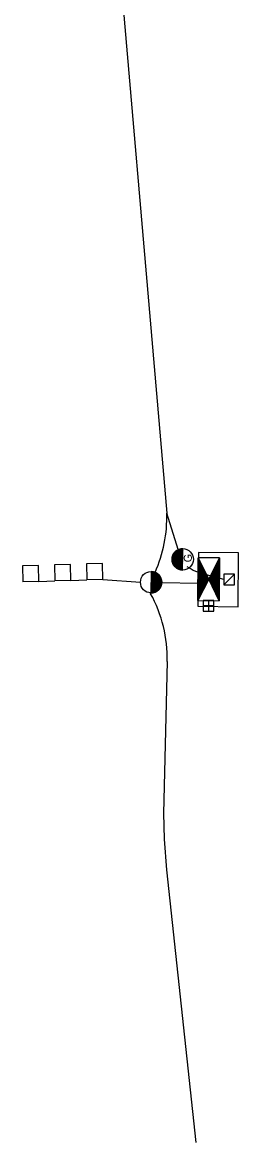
# Model space of a CAD drawing. Extents: x 584850 to 602551, y 145475 to 158627.
# Drawn here: x 585893.2 to 585974.3, y 152717.9 to 153137.7 of the extents above; entities that cross this region are included whole.
import ezdxf

# ---------------------------------------------------------------- set-up
doc = ezdxf.new("R2010")
doc.units = 0
doc.layers.add('Default', color=7, linetype='Continuous')

msp = doc.modelspace()

# ---------------------------------------------------------------- linework, layer by layer
at = {"layer": 'Default'}
for p, q in [((585951.7, 152940.13), (585947.39, 152953.8)), ((585953.38, 152940.5), (585949.39, 152936.66)), ((585953.45, 152940.24), (585949.4, 152936.33)), ((585953.45, 152939.9), (585949.42, 152936.02)), ((585953.01, 152940.47), (585949.43, 152937.03)), ((585953.44, 152939.56), (585949.47, 152935.74)), ((585952.6, 152940.41), (585949.49, 152937.42)), ((585952.14, 152940.3), (585949.65, 152937.9)), ((585951.52, 152940.04), (585949.94, 152938.52)), ((585950.79, 152939.54), (585953.39, 152936.84)), ((585950.98, 152939.69), (585953.4, 152937.18)), ((585951.18, 152939.83), (585953.4, 152937.52)), ((585951.39, 152939.96), (585953.41, 152937.86)), ((585951.61, 152940.08), (585953.41, 152938.2)), ((585951.84, 152940.18), (585953.42, 152938.54)), ((585952.08, 152940.28), (585953.43, 152938.88)), ((585952.34, 152940.35), (585953.43, 152939.22)), ((585952.61, 152940.42), (585953.44, 152939.56)), ((585952.9, 152940.47), (585953.45, 152939.9)), ((585953.21, 152940.49), (585953.45, 152940.24)), ((585953.31, 152932.5), (585953.46, 152940.5)), ((585953.41, 152940.5), (585953.46, 152940.46)), ((585949.4, 152936.83), (585953.31, 152932.77)), ((585949.4, 152936.49), (585953.23, 152932.51)), ((585949.4, 152936.14), (585952.86, 152932.54)), ((585949.45, 152937.13), (585953.32, 152933.11)), ((585949.48, 152935.72), (585952.46, 152932.62)), ((585949.49, 152937.43), (585953.33, 152933.45)), ((585953.43, 152939.22), (585949.53, 152935.45)), ((585949.58, 152937.69), (585953.33, 152933.79)), ((585953.43, 152938.88), (585949.61, 152935.2)), ((585949.66, 152937.94), (585953.34, 152934.13)), ((585953.42, 152938.54), (585949.71, 152934.96)), ((585949.76, 152938.18), (585953.34, 152934.47)), ((585953.41, 152938.2), (585949.81, 152934.72)), ((585949.88, 152938.41), (585953.35, 152934.81)), ((585953.41, 152937.86), (585949.93, 152934.51)), ((585950, 152938.63), (585953.36, 152935.15)), ((585953.4, 152937.52), (585950.06, 152934.3)), ((585950.14, 152938.83), (585953.36, 152935.49)), ((585953.4, 152937.18), (585950.2, 152934.1)), ((585950.29, 152939.02), (585953.37, 152935.82)), ((585953.39, 152936.84), (585950.35, 152933.92)), ((585950.44, 152939.21), (585953.38, 152936.16)), ((585953.38, 152936.5), (585950.51, 152933.73)), ((585950.62, 152939.37), (585953.38, 152936.5)), ((585953.38, 152936.16), (585950.68, 152933.57)), ((585953.37, 152935.82), (585950.87, 152933.41)), ((585953.36, 152935.49), (585951.05, 152933.26)), ((585957.29, 152937.49), (585957.19, 152937.44)), ((585959.92, 152935.65), (585959.19, 152934.94)), ((585960.03, 152935.42), (585959.19, 152934.6)), ((585959.59, 152936.33), (585959.2, 152935.96)), ((585959.7, 152936.1), (585959.2, 152935.62)), ((585959.81, 152935.88), (585959.2, 152935.28)), ((585960.47, 152934.51), (585959.2, 152935.81)), ((585960.8, 152933.83), (585959.2, 152935.47)), ((585959.48, 152936.56), (585959.21, 152936.83)), ((585959.37, 152936.79), (585959.21, 152936.64)), ((585959.48, 152936.56), (585959.21, 152936.3)), ((585959.81, 152935.88), (585959.21, 152936.49)), ((585960.14, 152935.2), (585959.21, 152936.15)), ((585959.26, 152937.01), (585959.22, 152936.98)), ((585967.2, 152935.38), (585965.56, 152933.78)), ((585967.2, 152935.72), (585965.9, 152934.45)), ((585967.21, 152936.06), (585966.25, 152935.13)), ((585967.19, 152934.51), (585966.37, 152935.35)), ((585967.19, 152934.85), (585966.48, 152935.58)), ((585967.21, 152936.4), (585966.6, 152935.8)), ((585967.2, 152935.19), (585966.6, 152935.8)), ((585967.2, 152935.53), (585966.71, 152936.03)), ((585967.21, 152935.87), (585966.83, 152936.25)), ((585967.21, 152936.2), (585966.94, 152936.48)), ((585967.22, 152936.74), (585966.95, 152936.48)), ((585967.21, 152936.54), (585967.06, 152936.7)), ((585967.22, 152936.88), (585967.18, 152936.93)), ((585899.24, 152934.19), (585893.24, 152934.01)), ((585893.24, 152934.01), (585893.43, 152928.01)), ((585899.43, 152928.2), (585899.24, 152934.19)), ((585911.23, 152934.57), (585905.24, 152934.38)), ((585905.24, 152934.38), (585905.43, 152928.39)), ((585911.42, 152928.58), (585911.23, 152934.57)), ((585923.23, 152934.95), (585917.23, 152934.76)), ((585917.23, 152934.76), (585917.42, 152928.77)), ((585923.42, 152928.96), (585923.23, 152934.95)), ((585941.59, 152931.94), (585941.44, 152923.95)), ((585941.54, 152929.3), (585943.64, 152931.32)), ((585941.54, 152928.96), (585943.85, 152931.19)), ((585941.55, 152929.98), (585943.2, 152931.57)), ((585941.55, 152929.64), (585943.42, 152931.45)), ((585941.56, 152930.32), (585942.95, 152931.66)), ((585941.57, 152931), (585942.43, 152931.83)), ((585941.57, 152930.66), (585942.71, 152931.76)), ((585941.58, 152931.34), (585942.15, 152931.88)), ((585945.45, 152927.32), (585941.58, 152931.34)), ((585941.59, 152931.94), (585941.59, 152931.94)), ((585941.59, 152931.94), (585941.59, 152931.94)), ((585941.59, 152931.68), (585941.85, 152931.93)), ((585945.5, 152927.62), (585941.59, 152931.68)), ((585945.5, 152927.96), (585941.67, 152931.94)), ((585945.49, 152928.31), (585942.04, 152931.9)), ((585945.42, 152928.73), (585942.44, 152931.82)), ((585942.59, 152930.69), (585943.01, 152931.63)), ((585945.3, 152929.2), (585942.92, 152931.67)), ((585945.03, 152929.83), (585943.54, 152931.38)), ((585949.6, 152935.24), (585951.98, 152932.77)), ((585949.87, 152934.62), (585951.36, 152933.07)), ((585953.36, 152935.15), (585951.26, 152933.13)), ((585953.35, 152934.81), (585951.48, 152933)), ((585953.34, 152934.47), (585951.7, 152932.88)), ((585953.34, 152934.13), (585951.94, 152932.79)), ((585953.33, 152933.79), (585952.19, 152932.69)), ((585953.33, 152933.45), (585952.47, 152932.62)), ((585953.32, 152933.11), (585952.75, 152932.57)), ((585953.31, 152932.77), (585953.05, 152932.52)), ((585953.31, 152932.5), (585953.31, 152932.51)), ((585953.31, 152932.5), (585953.31, 152932.51)), ((585954.91, 152933.85), (585955.77, 152933.34)), ((585962.02, 152931.33), (585959.12, 152928.49)), ((585961.69, 152932.01), (585959.13, 152929.51)), ((585961.8, 152931.78), (585959.13, 152929.17)), ((585961.91, 152931.55), (585959.13, 152928.83)), ((585961.36, 152932.69), (585959.14, 152930.53)), ((585961.47, 152932.46), (585959.14, 152930.19)), ((585961.58, 152932.24), (585959.14, 152929.85)), ((585961.14, 152933.15), (585959.15, 152931.21)), ((585961.25, 152932.92), (585959.15, 152930.87)), ((585962.55, 152927.93), (585959.15, 152931.4)), ((585960.8, 152933.83), (585959.16, 152932.22)), ((585960.91, 152933.6), (585959.16, 152931.88)), ((585961.03, 152933.37), (585959.16, 152931.55)), ((585962.9, 152928.6), (585959.16, 152932.42)), ((585962.78, 152928.38), (585959.16, 152932.08)), ((585962.66, 152928.15), (585959.16, 152931.74)), ((585960.47, 152934.51), (585959.17, 152933.24)), ((585960.58, 152934.28), (585959.17, 152932.9)), ((585960.69, 152934.06), (585959.17, 152932.56)), ((585963.13, 152929.05), (585959.17, 152933.1)), ((585963.01, 152928.83), (585959.17, 152932.76)), ((585960.25, 152934.97), (585959.18, 152933.92)), ((585960.36, 152934.74), (585959.18, 152933.58)), ((585962.13, 152931.1), (585959.18, 152934.11)), ((585962.46, 152930.42), (585959.18, 152933.77)), ((585962.8, 152929.73), (585959.18, 152933.43)), ((585960.14, 152935.19), (585959.19, 152934.26)), ((585961.14, 152933.15), (585959.19, 152935.13)), ((585961.47, 152932.46), (585959.19, 152934.79)), ((585961.8, 152931.78), (585959.19, 152934.45)), ((585967.17, 152933.01), (585963.13, 152929.05)), ((585967.17, 152932.67), (585963.24, 152928.82)), ((585967.17, 152932.33), (585963.35, 152928.6)), ((585967.16, 152931.99), (585963.46, 152928.37)), ((585967.18, 152933.35), (585963.47, 152929.73)), ((585967.16, 152931.65), (585963.57, 152928.14)), ((585967.15, 152931.31), (585963.68, 152927.91)), ((585967.18, 152933.69), (585963.82, 152930.4)), ((585967.19, 152934.03), (585964.17, 152931.08)), ((585967.12, 152928.4), (585964.28, 152931.3)), ((585967.13, 152928.74), (585964.4, 152931.53)), ((585967.19, 152934.37), (585964.52, 152931.75)), ((585967.13, 152929.08), (585964.52, 152931.75)), ((585967.13, 152929.42), (585964.63, 152931.98)), ((585967.14, 152929.76), (585964.75, 152932.2)), ((585967.19, 152934.7), (585964.86, 152932.43)), ((585967.14, 152930.1), (585964.86, 152932.43)), ((585967.15, 152930.43), (585964.98, 152932.65)), ((585967.15, 152930.77), (585965.09, 152932.88)), ((585967.2, 152935.04), (585965.21, 152933.1)), ((585967.15, 152931.11), (585965.21, 152933.1)), ((585967.16, 152931.45), (585965.33, 152933.33)), ((585967.16, 152931.79), (585965.44, 152933.55)), ((585967.16, 152932.13), (585965.56, 152933.78)), ((585967.17, 152932.47), (585965.67, 152934)), ((585967.17, 152932.81), (585965.79, 152934.23)), ((585967.18, 152933.15), (585965.9, 152934.45)), ((585967.18, 152933.49), (585966.02, 152934.68)), ((585967.18, 152933.83), (585966.13, 152934.9)), ((585967.19, 152934.17), (585966.25, 152935.13)), ((585899.43, 152928.2), (585893.43, 152928.01)), ((585899.43, 152928.2), (585905.43, 152928.39)), ((585911.42, 152928.58), (585905.43, 152928.39)), ((585911.42, 152928.58), (585917.42, 152928.77)), ((585923.42, 152928.96), (585917.42, 152928.77)), ((585923.42, 152928.96), (585937.52, 152927.9)), ((585941.45, 152924.55), (585945.48, 152928.43)), ((585941.45, 152924.21), (585945.5, 152928.12)), ((585941.46, 152924.89), (585945.43, 152928.71)), ((585941.47, 152925.57), (585945.29, 152929.24)), ((585941.47, 152925.23), (585945.37, 152928.99)), ((585941.48, 152926.25), (585945.09, 152929.72)), ((585941.48, 152925.91), (585945.19, 152929.49)), ((585941.49, 152926.59), (585944.97, 152929.94)), ((585941.5, 152927.27), (585944.7, 152930.35)), ((585941.5, 152926.93), (585944.84, 152930.15)), ((585943.92, 152924.75), (585941.5, 152927.27)), ((585943.72, 152924.62), (585941.5, 152926.93)), ((585941.51, 152927.61), (585944.55, 152930.53)), ((585944.11, 152924.91), (585941.51, 152927.61)), ((585941.52, 152928.28), (585944.22, 152930.88)), ((585941.52, 152927.94), (585944.39, 152930.72)), ((585944.46, 152925.24), (585941.52, 152928.28)), ((585944.28, 152925.07), (585941.52, 152927.94)), ((585941.52, 152923.95), (585945.51, 152927.79)), ((585941.53, 152928.62), (585944.03, 152931.04)), ((585944.61, 152925.43), (585941.53, 152928.62)), ((585944.9, 152925.82), (585941.54, 152929.3)), ((585944.76, 152925.62), (585941.54, 152928.96)), ((585945.14, 152926.26), (585941.55, 152929.98)), ((585945.02, 152926.04), (585941.55, 152929.64)), ((585945.24, 152926.5), (585941.56, 152930.32)), ((585945.41, 152927.02), (585941.57, 152931)), ((585945.32, 152926.76), (585941.57, 152930.66)), ((585941.89, 152923.98), (585945.47, 152927.42)), ((585942.3, 152924.03), (585945.41, 152927.03)), ((585945.52, 152927.87), (585959.11, 152927.53)), ((585962.09, 152927.03), (585959.07, 152924.08)), ((585963.13, 152929.05), (585959.08, 152925.1)), ((585962.78, 152928.38), (585959.08, 152924.76)), ((585962.43, 152927.7), (585959.08, 152924.42)), ((585962.8, 152929.73), (585959.09, 152926.12)), ((585962.91, 152929.51), (585959.09, 152925.78)), ((585963.02, 152929.28), (585959.09, 152925.44)), ((585962.57, 152930.19), (585959.1, 152926.79)), ((585962.68, 152929.96), (585959.1, 152926.45)), ((585961.05, 152925), (585959.1, 152926.99)), ((585962.24, 152930.87), (585959.11, 152927.81)), ((585962.35, 152930.64), (585959.11, 152927.47)), ((585962.46, 152930.42), (585959.11, 152927.13)), ((585961.28, 152925.45), (585959.11, 152927.66)), ((585961.16, 152925.23), (585959.11, 152927.33)), ((585962.13, 152931.1), (585959.12, 152928.15)), ((585961.62, 152926.13), (585959.12, 152928.68)), ((585961.51, 152925.9), (585959.12, 152928.34)), ((585961.39, 152925.68), (585959.12, 152928)), ((585961.97, 152926.8), (585959.13, 152929.7)), ((585961.86, 152926.58), (585959.13, 152929.36)), ((585961.74, 152926.35), (585959.13, 152929.02)), ((585962.2, 152927.25), (585959.14, 152930.38)), ((585962.09, 152927.03), (585959.14, 152930.04)), ((585962.43, 152927.7), (585959.15, 152931.06)), ((585962.32, 152927.48), (585959.15, 152930.72)), ((585968.82, 152928.99), (585962.28, 152930.66)), ((585967.08, 152925), (585963.13, 152929.05)), ((585967.09, 152925.34), (585963.24, 152929.28)), ((585967.09, 152925.68), (585963.36, 152929.5)), ((585967.08, 152924.66), (585963.46, 152928.37)), ((585967.1, 152926.02), (585963.47, 152929.73)), ((585967.1, 152926.36), (585963.59, 152929.95)), ((585967.1, 152926.7), (585963.71, 152930.18)), ((585967.15, 152930.97), (585963.79, 152927.69)), ((585967.08, 152924.32), (585963.79, 152927.69)), ((585967.11, 152927.04), (585963.82, 152930.4)), ((585967.15, 152930.63), (585963.9, 152927.46)), ((585967.11, 152927.38), (585963.94, 152930.63)), ((585967.14, 152930.29), (585964.01, 152927.23)), ((585967.11, 152927.72), (585964.05, 152930.85)), ((585967.14, 152929.95), (585964.12, 152927)), ((585967.07, 152923.98), (585964.12, 152927)), ((585967.12, 152928.06), (585964.17, 152931.08)), ((585967.14, 152929.61), (585964.23, 152926.78)), ((585967.13, 152929.28), (585964.34, 152926.55)), ((585967.13, 152928.94), (585964.45, 152926.32)), ((585967.12, 152928.6), (585964.56, 152926.09)), ((585967.12, 152928.26), (585964.68, 152925.87)), ((585967.12, 152927.92), (585964.79, 152925.64)), ((585967.11, 152927.58), (585964.9, 152925.41)), ((585967.11, 152927.24), (585965.01, 152925.18)), ((585968.8, 152926.99), (585972.84, 152930.94)), ((585941.16, 152923.96), (585941.35, 152923.61)), ((585941.49, 152923.95), (585941.44, 152923.99)), ((585942, 152923.98), (585941.45, 152924.55)), ((585941.69, 152923.96), (585941.45, 152924.21)), ((585942.29, 152924.03), (585941.46, 152924.89)), ((585942.82, 152924.17), (585941.47, 152925.57)), ((585942.56, 152924.1), (585941.47, 152925.23)), ((585943.29, 152924.37), (585941.48, 152926.25)), ((585943.06, 152924.27), (585941.48, 152925.91)), ((585943.51, 152924.49), (585941.49, 152926.59)), ((585942.76, 152924.14), (585945.25, 152926.54)), ((585943.38, 152924.41), (585944.96, 152925.93)), ((585960.35, 152923.65), (585959.05, 152922.38)), ((585960.01, 152922.98), (585959.05, 152922.04)), ((585961.39, 152925.68), (585959.06, 152923.4)), ((585961.05, 152925), (585959.06, 152923.06)), ((585960.7, 152924.33), (585959.06, 152922.72)), ((585959.77, 152922.53), (585959.06, 152923.25)), ((585959.66, 152922.3), (585959.06, 152922.91)), ((585961.74, 152926.35), (585959.07, 152923.74)), ((585960.12, 152923.2), (585959.07, 152924.27)), ((585960, 152922.98), (585959.07, 152923.93)), ((585959.89, 152922.75), (585959.07, 152923.59)), ((585960.35, 152923.65), (585959.08, 152924.95)), ((585960.24, 152923.43), (585959.08, 152924.61)), ((585960.7, 152924.33), (585959.09, 152925.97)), ((585960.58, 152924.1), (585959.09, 152925.63)), ((585960.47, 152923.88), (585959.09, 152925.29)), ((585960.93, 152924.78), (585959.1, 152926.65)), ((585960.81, 152924.55), (585959.1, 152926.31)), ((585967.07, 152923.65), (585964.45, 152926.32)), ((585967.07, 152923.31), (585964.79, 152925.64)), ((585967.11, 152926.9), (585965.12, 152924.96)), ((585967.06, 152922.97), (585965.12, 152924.95)), ((585967.1, 152926.56), (585965.23, 152924.73)), ((585967.1, 152926.22), (585965.34, 152924.5)), ((585967.09, 152925.88), (585965.45, 152924.27)), ((585967.06, 152922.63), (585965.45, 152924.27)), ((585967.09, 152925.54), (585965.56, 152924.05)), ((585967.09, 152925.2), (585965.67, 152923.82)), ((585967.08, 152924.86), (585965.78, 152923.59)), ((585967.05, 152922.29), (585965.78, 152923.59)), ((585967.08, 152924.52), (585965.89, 152923.36)), ((585967.08, 152924.18), (585966, 152923.14)), ((585967.07, 152923.85), (585966.11, 152922.91)), ((585967.05, 152921.95), (585966.11, 152922.91)), ((585967.07, 152923.51), (585966.22, 152922.68)), ((585967.06, 152923.17), (585966.33, 152922.45)), ((585967.06, 152922.83), (585966.45, 152922.23)), ((585959.31, 152921.63), (585959.04, 152921.36)), ((585959.19, 152921.4), (585959.04, 152921.55)), ((585959.08, 152921.18), (585959.04, 152921.22)), ((585959.66, 152922.3), (585959.05, 152921.7)), ((585959.43, 152921.85), (585959.05, 152922.23)), ((585959.31, 152921.63), (585959.05, 152921.89)), ((585959.54, 152922.08), (585959.06, 152922.57)), ((585965.02, 152919.03), (585961.02, 152919.08)), ((585963.04, 152921.05), (585963, 152917.05)), ((585967.05, 152921.61), (585966.45, 152922.22)), ((585967.06, 152922.49), (585966.56, 152922)), ((585967.05, 152922.15), (585966.67, 152921.77)), ((585967.05, 152921.81), (585966.78, 152921.54)), ((585967.04, 152921.27), (585966.78, 152921.54)), ((585967.05, 152921.47), (585966.89, 152921.32)), ((585967.04, 152921.13), (585967, 152921.09))]:
    msp.add_line(p, q, dxfattribs=at)
for points in [[(585924.77, 153215.78), (585947.39, 152953.8)], [(585972.84, 152930.94), (585968.8, 152926.99), (585972.8, 152926.94), (585972.84, 152930.94)], [(585972.8, 152926.94), (585972.84, 152930.94), (585968.8, 152926.99), (585972.8, 152926.94)], [(585972.84, 152930.94), (585968.8, 152926.99), (585972.8, 152926.94), (585972.84, 152930.94)], [(585972.84, 152930.94), (585968.8, 152926.99), (585972.8, 152926.94), (585972.84, 152930.94)], [(585947.55, 152898.24), (585946.27, 152846.32)], [(585947.34, 152820.2), (585958.25, 152717.94)]]:
    msp.add_lwpolyline(points, dxfattribs=at)
for points in [[(585959.24, 152939.09), (585959.02, 152918.9), (585974.11, 152918.73), (585974.34, 152938.93)], [(585959.22, 152937.1), (585959.04, 152921.1), (585967.04, 152921.01), (585967.22, 152937.01)], [(585959.22, 152937.1), (585963.13, 152929.05), (585959.04, 152921.1)], [(585967.22, 152937.01), (585967.04, 152921), (585963.13, 152929.05)], [(585968.84, 152930.99), (585968.8, 152926.99), (585972.8, 152926.94), (585972.84, 152930.94)], [(585961.04, 152921.08), (585961, 152917.08), (585964.99, 152917.03), (585965.04, 152921.03)]]:
    msp.add_lwpolyline(points, close=True, dxfattribs=at)
for centre in [(585953.38, 152936.5), (585941.52, 152927.94)]:
    msp.add_circle(centre, 4, dxfattribs=at)
for centre, radius, start, end in [((585897.42, 152952.16), 50, 335.7551, 1.8828), ((585953.38, 152936.5), 4, 88.9257, 268.9257), ((585941.52, 152927.94), 4, 268.9257, 88.9257), ((585968.45, 152954.88), 25, 239.522, 255.6978), ((585897.56, 152899.47), 50, 358.5933, 28.8669), ((586146.21, 152841.41), 200, 178.5933, 186.0885)]:
    msp.add_arc(centre, radius, start, end, dxfattribs=at)

# ---------------------------------------------------------------- texts
msp.add_text('G', height=3, rotation=89.3623, dxfattribs=at).set_placement((585956.76, 152935.37))

doc.saveas('drawing.dxf')
